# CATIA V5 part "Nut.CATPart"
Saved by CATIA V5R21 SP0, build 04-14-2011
Part number: nut
Bounding box of the stored display mesh (mm): x -13.856 to 13.856, y 0 to 9, z -12 to 12
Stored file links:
  D:\CATIA V5R21 E-RESOURCES\CATIA-V5R21\catia-v5r21-Prts\c12_catia_v5r21_prt\c12_catia_v5r21figr_12-49\Nut.CATPart
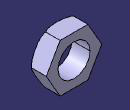
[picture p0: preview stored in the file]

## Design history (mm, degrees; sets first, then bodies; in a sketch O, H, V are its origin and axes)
Body1 (main body)
  Sketch1 on zx-plane, origin (0, 0, 0), H (-1, 0, 0), V (0, 0, 1)
    circle A1 centre (0, 0) radius 8
    construction circle A2 centre (0, 0) radius 12
    point P1 (-6.9282, -12)
    point P2 (6.9282, -12)
    point P3 (13.8564, 0)
    point P4 (6.9282, 12)
    point P5 (-6.9282, 12)
    point P6 (-13.8564, 0)
    point P7 (0, -12)
    line L1 (-6.9282, -12) -> (6.9282, -12)
    line L2 (6.9282, -12) -> (13.8564, 0)
    line L3 (13.8564, 0) -> (6.9282, 12)
    line L4 (6.9282, 12) -> (-6.9282, 12)
    line L5 (-6.9282, 12) -> (-13.8564, 0)
    line L6 (-13.8564, 0) -> (-6.9282, -12)
    construction line L7 (0, 0) -> (0, -12)
    construction circle A3 centre (0, 0) radius 13.8564
    construction arc A4 centre (-6.9282, 12) radius 13.8564 from (6.9282, 12) to (-13.8564, 0) cw
    construction arc A5 centre (6.9282, -12) radius 13.8564 from (13.8564, 0) to (-6.9282, -12) ccw
    radius A1 = 8
    radius A2 = 12
    coincidence: P7 A2, A3 P1, A3 P2, A3 P3, A3 P4, A3 P5, A3 P6, A4 O, A5 O
    vertical: L7 V
    midpoint: P7 L1
    parallelism: L1 L4
  Pad1: profile Sketch1, direction (0, 1, 0), length 9
  Sketch2 on xy-plane, origin (0, 0, 0), H (1, 0, 0), V (0, 1, 0)
    projected line E1 (10.7061, 0) -> (13.8564, 0) from edge of Pad1
    point P1 (13.8564, 0)
    projected line E2 (13.8564, 0) -> (13.8564, 1.8188) from edge of Pad1
    point P2 (13.8564, 0)
    arc A1 centre (10.7061, 3.6376) radius 3.6376 from (10.7061, 0) to (13.8564, 1.8188) ccw
    coincidence: P1 P2
    tangency: A1 E1
  Groove1: profile Sketch2, axis axis of face of Pad1, angle 360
